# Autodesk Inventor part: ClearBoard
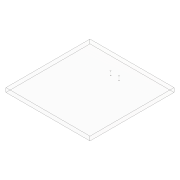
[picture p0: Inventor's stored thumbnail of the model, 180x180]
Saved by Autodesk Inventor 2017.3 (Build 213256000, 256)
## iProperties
Part Number: ClearBoard
Material: PET プラスチック
Document SubType Name: Modeling
Designer: kyushu-hep
Density: 1.541 g/cm^3
Appearance: ポリカーボネート - クリア
Author: kyushu-hep
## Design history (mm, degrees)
sketch "スケッチ1"
  geometry: L1 (50, -50)-(-50, -50); L2 (-50, -50)-(-50, 50); L3 (-50, 50)-(50, 50); L4 (50, 50)-(50, -50); L5 (50, -50)-(-50, 50); L6 (-50, -50)-(50, 50); 1 further point
  constraints: 12 end point, 2 midpoint, 2 parallel, 1 horizontal, 1 perpendicular
  dimensions: "d0" = 100 distance of L2.end L3.end; "d1" = 100 distance of L1.end L2.end
extrude "押し出し1" new body sketch "スケッチ1" distance "d2" = 5; taper "d3" = 0 deg
sketch "スケッチ2"
  geometry: L1 (-100, 50)-(-100, -50); L2 (-100, -50)-(100, -50); C1 r 0.5 at (-5.05, 29.5); C2 r 0.5 at (5.05, 29.5); 2 further points
  constraints: 4 end point, 2 centre point
  dimensions: "d4" = 1 diameter of C1; "d5" = 1 diameter of C2; "d6" = 10.1 distance of C2.centre C1.centre; "d7" = 29.5 vertical distance of point (0, 0) C2.centre; "d8" = 5.05 horizontal distance of C1.centre point (0, 0)
extrude "押し出し2" cut sketch "スケッチ2" distance "d9" = 5; taper "d10" = 0 deg
node "ソリッド1"
